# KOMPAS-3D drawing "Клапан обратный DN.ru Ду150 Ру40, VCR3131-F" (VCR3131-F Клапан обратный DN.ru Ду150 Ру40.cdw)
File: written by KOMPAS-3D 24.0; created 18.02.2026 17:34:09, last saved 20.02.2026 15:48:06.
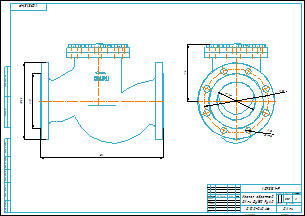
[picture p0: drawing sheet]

Document properties: art: D100-04046; Автор: R2D2; Форматы листов документа: A2; Полное имя файла: VCR3131-F Клапан обратный DN.ru Ду150 Ру40.m3d; Масса: 53.5; Наименование: Клапан обратный DN.ru Ду150 Ру40; Количество листов документа: 1; Примечание: D100-04046

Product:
- Part/product: Клапан обратный DN.ru Ду150 Ру40  | designation VCR3131-F
    Масса: 53.5
    Примечание: D100-04046
    additional columns: D100-04046

Views: Вид 1, Спереди, Проекционный вид 2
Referenced files in E:\Работа\Зайцев\VCR3131-F Клапан обратный DN.ru Ду15-300\DN150\: VCR3131-F Клапан обратный DN.ru Ду150 Ру40.m3d
Referenced files in E:\Работа\Зайцев\Для компаса\: чертеж DN.ru А3.cdt
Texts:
  VCR3131-F
  чертеж DN.ru А3.cdt
  Клапан обратный
  DN.ru Ду150 Ру40
  prop
  Клапан обратный DN.ru Ду150 Ру40
  VCR3131-F Клапан обратный DN.ru Ду150 Ру40
Dimensions and other numbers on the sheet: 0; 3; 2; 4; 220; 26; 8 отв.; 250; 150; 480; 212; 300; 1:2; 1; 53,5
